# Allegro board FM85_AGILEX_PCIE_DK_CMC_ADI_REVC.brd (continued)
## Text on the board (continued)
User.18: C1448 | C1449 | C1439 | C1431 | C1177 | C1176 | R457 | C491 | C493 | C492 | R501 | R503 | R504 | R360 | R482 | R814 | R478 | R481 | R480 | R614 | C716 | R580 | R613 | R604 | R578 | R579 | R585 | R615 | R601 | R582 | R607 | R583 | R431 | C760 | R620 | R609 | R587 | R584 | R603 | R429 | R430 | R432 | R433 | R434 | R189 | R828 | R829 | R832 | R492 | R496 | R497 | C473 | R830 | C474 | R490 | R485 | R827 | C589 | C475 | C999 | C476 | R831 | R671 | R571 | R833 | C695 | R672 | R567 | C1000 | R568 | C692 | R834 | R970 | R668 | R572 | C1366 | R978 | R981 | R994 | C1345 | R995 | R980 | R801 | C1367 | C1346 | C1372 | R629 | R640 | R631 | FB27 | R688 | R683 | C850 | R692 | C849 | R538 | R537 | R532 | R534 | C772 | C610 | R625 | R639 | R536 | R531 | R529 | R630 | C774 | R632 | R684 | R903 | R694 | R686 | R65 | R901 | C196 | R73 | R74 | R52 | R905 | R899 | FB21 | FB20 | FB19 | FB18 | C146 | C158 | C155 | C145 | C153 | R475 | C156 | R474 | ST5 | C568 | C569 | ST4 | C100 | C109 | C395 | FB1 | C114 | C244 | R103 | R89 | C99 | C113 | C210 | R116 | R118 | R117 | R91 | C200 | C259 | C222 | C238 | C389 | C221 | C241 | C111 | C199 | C245 | C211 | C237 | C242 | C201 | C202 | C243 | C1138 | R92 | R105 | R93 | R106 | R220 | C1 | C10 | C352 | R221 | R973 | C351 | R952 | R975 | R951 | C1162 | R75 | C350 | C349 | C393 | C12 | R99 | R83 | C1224 | C1417 | C1054 | C203 | C239 | C209 | C235 | C348 | C347 | C1235 | C1416 | C207 | C233 | R37 | C2 | C11 | C1090 | C257 | C1426 | C1238 | C1234 | C205 | C1093 | R109 | R111 | R110 | C1236 | C1233 | C208 | C346 | C204 | C240 | C236 | C345 | R82 | R114 | C1232 | R113 | R115 | C258 | C225 | C206 | C234 | C9 | R120 | C1189 | C344 | C343 | C1285 | C1050 | C1407 | C1147 | C1148 | C47 | C61 | C342 | C1149 | R218 | C341 | R219 | R217 | C1043 | R146 | R215 | C1322 | C1099 | C1100 | R119 | C1280 | C339 | C1324 | C1272 | R214 | C338 | C1098 | C60 | R678 | R677 | R937 | R961 | R140 | C337 | R179 | C336 | R963 | C329 | C48 | C56 | R165 | R666 | R665 | C334 | C332 | C62 | C55 | C328 | C326 | R30 | R76 | C198 | R876 | C220 | C197 | C322 | R879 | C320 | R27 | R35 | R877 | C98 | R36 | C318 | C317 | R14 | R881 | R875 | R163 | C310 | C309 | C325 | C308 | R162 | R715 | C324 | R726 | R717 | C316 | C315 | R453 | C314 | C313 | C312 | C311 | C230 | C264 | C880 | C983 | R817 | C229 | C232 | R160 | R815 | R818 | R816 | R711 | R725 | C321 | C882 | R716 | R740 | C307 | R718 | C306 | R1000 | R1001 | C1389 | C1294 | C1293 | C290 | C275 | C282 | C267 | C1392 | R154 | C1342 | R173 | R153 | C435 | C271 | R149 | FB7 | C436 | C441 | C286 | C432 | C1343 | R445 | C462 | C444 | R447 | C560 | C459 | R446 | R451 | C456 | R239 | C280 | C265 | R444 | R436 | R390 | R399 | R437 | R403 | R438 | R439 | R393 | R389 | R441 | R388 | C557 | C555 | R442 | R837 | R836 | R212 | R464 | C524 | C391 | R469 | C567 | C539 | C514 | R468 | C553 | R466 | R211 | R424 | R463 | C482 | C481 | C518 | C517 | R425 | C549 | C521 | R467 | R323 | R324 | R421 | C548 | L14 | R462 | R322 | C515 | R325 | R420 | C546 | R423 | C495 | C526 | C528 | C738 | R418 | L12 | C532 | R130 | R135 | R417 | C301 | C488 | C487 | R134 | C302 | C512 | R595 | R341 | R346 | C730 | C304 | R345 | R340 | C303 | R344 | R339 | R125 | C735 | L13 | R332 | R596 | R860 | C295 | R864 | C490 | C489 | C739 | C296 | R349 | R353 | C503 | C509 | R348 | R352 | R354 | R355 | R347 | R351 | C506 | C507 | R350 | R773 | C505 | R781 | C499 | R381 | R342 | R382 | R343 | R317 | R318 | R319 | R320 | R412 | R338 | C496 | R375 | C1132 | R411 | C520 | C531 | R112 | R190 | R191 | R194 | R197 | R939 | R941 | C1128 | C1112 | C1130 | C1129 | C1279 | C1111 | C1122 | C1123 | C1121 | C1168 | C1175 | C1170 | C1421 | C1418 | C1419 | C1163 | C1097 | C1260 | C1244 | C1202 | C1094 | C1201 | C1095 | C1261 | C424 | C1096 | C1203 | C1425 | C1204 | C1029 | C1197 | C1198 | C1237 | C1192 | C1214 | C1042 | C1186 | C1210 | C1209 | C417 | C1159 | C1160 | C1255 | C1256 | C1283 | C1259 | C1258 | C1257 | C1262 | C1267 | C1058 | C1034 | C1041 | R866 | R856 | R867 | C1273 | R936 | R142 | R143 | R139 | R141 | R138 | C1263 | C1284 | C1307 | C1308 | C1320 | C1318 | C1126 | C1445 | C1319 | C1317 | C1125 | C1119 | C1124 | C1446 | C1154 | C1153 | R803 | R809 | R808 | C975 | R806 | R812 | R813 | R802 | R805 | R807 | R811 | C976 | R502 | R621 | R622 | C725 | R586 | C727 | R590 | TP10 | C356 | C357 | C360 | C361 | C364 | C365 | C368 | C369 | C379 | C380 | C383 | C384 | C387 | C388 | C375 | C376 | TP21 | C366 | C367 | C354 | C355 | C358 | C359 | C362 | C363 | R185 | R186 | ST27 | R669 | C373 | C374 | C381 | C382 | C385 | C386 | C377 | C378 | R670 | R676 | R679 | R972 | R967 | C1400 | C824 | R674 | R675 | R957 | R960 | TP20 | C986 | R792 | R852 | C1014 | C1015 | R846 | R826 | C998 | R794 | R798 | R790 | R796 | R795 | C966 | R793 | R799 | R800 | R789 | R825 | R850 | R849 | C1012 | C967 | TP22 | TP19 | TP11 | R551 | C599 | C600 | R559 | R506 | R513 | TP2 | R524 | R521 | R520 | R518 | R515 | R512 | R511 | R509 | TP4 | R527 | R526 | C607 | TP3 | TP16 | R533 | R550 | C633 | R553 | R554 | C713 | R573 | C701 | R576 | R577 | C690 | R563 | C675 | R565 | R566 | C668 | R558 | C656 | R560 | R561 | C700 | C674 | C655 | C632 | C699 | C673 | C654 | C631 | C697 | C671 | C652 | C629 | C664 | C665 | C645 | C644 | C682 | C684 | C709 | C708 | C711 | C688 | C666 | C647 | C1120 | C1265 | C1118 | C1117 | C1241 | C1045 | C1046 | C1242 | C1161 | C1180 | C1061 | C1183 | C1182 | C1104 | C1102 | C1103 | C1184 | C1181 | C1185 | C1325 | C1113 | C1101 | C1062 | C1239 | C1243 | C1047 | C1240 | C1152 | TP17 | C809 | C566 | C901 | R458 | R456 | R455 | R454 | R931 | R930 | C486 | R859 | R858 | R663 | C808 | R929 | R928 | R731 | R729 | R739 | R738 | R732 | C900 | R734 | R735 | R728 | R737 | R733 | R333 | R331 | R988 | R267 | R987 | R268 | R986 | C1332 | C446 | C445 | R234 | R233 | R230 | R229 | R223 | C448 | C447 | R985 | C1328 | R270 | R983 | R252 | R254 | R255 | R256 | R248 | R247 | R272 | R271 | R269 | R949 | C1331 | R170 | R172 | R263 | R264 | R237 | R238 | R235 | R236 | C453 | C454 | R784 | R783 | R788 | R786 | R426 | C952 | R785 | R787 | ST24 | R427 | C950 | R428 | R314 | R313 | C479 | R306 | R862 | R308 | C478 | ST29 | TP1 | R861 | C497 | C944 | R777 | ST23 | C498 | C948 | R776 | U35 | R363 | R361 | R359 | R356 | R364 | R362 | R358 | R357 | R982 | C561 | R365 | R368 | R366 | R370 | R369 | R367 | C572 | C573 | R477 | C1286 | R854 | R448 | R449 | R450 | C562 | R452 | R414 | R416 | R415 | R486 | R371 | ST26 | R484 | C579 | R479 | C715 | C751 | FB24 | R617 | R612 | ST3 | R588 | C750 | R616 | R618 | R619 | R589 | R608 | R611 | R581 | C720 | C726 | R602 | R606 | R187 | R293 | R487 | R488 | C587 | R489 | C1399 | R188 | R292 | R291 | R303 | R304 | R294 | R993 | C1397 | R996 | FB13 | R493 | R491 | R495 | R997 | R546 | R547 | C1398 | C472 | R998 | C471 | ST10 | R569 | R570 | C694 | C370 | C371 | C1368 | R969 | R933 | R932 | C1395 | R935 | R934 | C1396 | R971 | C1388 | C1347 | R958 | R976 | R965 | R966 | R977 | C685 | ST32 | C1369 | R959 | C1356 | R964 | R955 | ST28 | ST25 | R979 | C1348 | C687 | ST31 | R624 | R627 | R633 | C372 | ST13 | R690 | C848 | R626 | R628 | C782 | R641 | R634 | FB17 | R687 | C214 | C248 | C602 | C223 | C250 | C613 | R564 | R507 | R508 | R516 | R517 | R575 | C609 | R530 | R535 | R70 | R72 | R906 | R909 | C191 | R911 | R898 | R68 | R67 | R900 | R55 | R689 | R685 | R695 | C858 | R682 | C773 | R635 | ST6 | C611 | C617 | C612 | C616 | R926 | C194 | R51 | R57 | R59 | R914 | R915 | R902 | R896 | R892 | R894 | R691 | R680 | R693 | R681 | R53 | R61 | R60 | R54 | R58 | R913 | R904 | R895 | R893 | R63 | R56 | C192 | R62 | R908 | R907 | R910 | R912 | C653 | C698 | C630 | C672 | R66 | R897 | R71 | R69 | C178 | C169 | C186 | C165 | C177 | C151 | C160 | C163 | C710 | C683 | C663 | C646 | C189 | C185 | C175 | C187 | R48 | C190 | C176 | C150 | C188 | C161 | R46 | C172 | C180 | C182 | C181 | C166 | C179 | C148 | C154 | C162 | R555 | R522 | R476 | R465 | C168 | R556 | R528 | C167 | C571 | C157 | C164 | R47 | C159 | C183 | C174 | C147 | C184 | R45 | C173 | C570 | C1167 | R470 | R471 | R472 | R473 | C131 | C137 | C136 | C118 | C134 | C102 | C107 | C117 | C143 | C144 | C128 | C123 | R42 | C1116 | C1127 | C122 | C129 | C108 | C101 | C142 | R40 | C126 | R88 | R87 | R90 | R104 | C132 | C135 | C141 | C120 | C133 | C104 | C112 | C116 | R927 | C140 | C121 | R196 | R108 | R195 | C110 | C119 | R41 | C139 | C130 | C115 | C105 | C138 | R39 | C127 | ST12 | ST11 | C1247 | C33 | C41 | C42 | C21 | C36 | C4 | C13 | C18 | C213 | C226 | C251 | C249 | C215 | C224 | C247 | C260 | C23 | C24 | C16 | C22 | R3 | C25 | C30 | C14 | C3 | C46 | R1 | C28 | C1092 | R38 | C35 | C37 | C40 | C20 | C34 | C7 | C15 | C19 | C43 | R98 | C38 | C1091 | C31 | C39 | R4 | R97 | C44 | C32 | C17 | C6 | C45 | R2 | C29 | R79 | C1178 | C81 | C83 | C89 | C68 | R102 | R86 | C80 | C50 | C63 | C64 | C1179 | C69 | C88 | R145 | C263 | C58 | C67 | R9 | R216 | R209 | C256 | C92 | C78 | C59 | C49 | C87 | R7 | C74 | C231 | R213 | C392 | C1326 | R178 | C79 | C86 | C91 | C66 | R210 | C82 | C52 | C57 | C65 | C90 | C85 | R81 | C76 | C84 | R10 | C70 | C77 | C53 | C71 | R8 | C75 | R80 | R34 | R882 | R885 | R887 | R874 | R17 | C93 | R32 | R29 | C892 | C94 | R865 | R13 | R19 | R21 | R890 | R891 | R878 | R872 | R868 | R870 | R15 | ST16 | ST15 | R23 | R22 | R16 | R20 | R157 | R889 | R880 | R871 | R869 | R156 | R999 | R25 | R18 | C95 | R24 | R710 | R713 | R719 | R884 | R883 | R886 | R888 | R28 | R873 | R31 | R33 | R714 | C890 | R727 | R712 | R720 | R460 | R921 | C1313 | R925 | R923 | R819 | R656 | ST20 | C1312 | R820 | C985 | C565 | ST9 | R85 | R101 | R84 | R100 | C1310 | C977 | R662 | R660 | R917 | R329 | R330 | C483 | ST18 | R916 | R918 | R920 | FB40 | C881 | R721 | R605 | R610 | ST17 | C1391 | C1390 | R183 | R184 | C353 | FB10 | R942 | R327 | R328 | C484 | C438 | FB8 | FB6 | R151 | R155 | R435 | ST30 | C558 | C434 | C433 | C430 | C442 | C443 | C428 | C431 | C340 | R174 | R440 | R443 | R224 | R948 | R946 | C461 | C458 | R228 | C427 | FB5 | C440 | C425 | C426 | C437 | C439 | C429 | R129 | R128 | R124 | R133 | C460 | C457 | C463 | R126 | R127 | R123 | R132 | R122 | R121 | FB9 | R387 | R386 | R392 | R394 | R395 | R400 | R379 | R158 | R422 | R419 | R175 | R171 | R380 | R401 | R397 | R398 | R396 | R402 | C559 | C542 | C536 | C552 | C556 | C390 | C534 | C535 | C1006 | C551 | C533 | R840 | R839 | R838 | C511 | C554 | C519 | C300 | C299 | C540 | C522 | R598 | R591 | R593 | C529 | C530 | C545 | C538 | C537 | R597 | ST2 | C729 | L11 | C733 | ST1 | R599 | R385 | C305 | C508 | C510 | R594 | R592 | R600 | R384 | C501 | R137 | R131 | C298 | C297 | R136 | R204 | R206 | R207 | R208 | R316 | R315 | R857 | R337 | R321 | R326 | R413 | R409 | R408 | R287 | R286 | R285 | R284 | R383 | R374 | C504 | R373 | R288 | R281 | R282 | R283 | R203 | R199 | R205 | R200 | R202 | R201 | R198 | C1447 | C1248 | C1131 | C1114 | C396 | C1173 | C1315 | C1169 | C1144 | C1146 | C1145 | C1408 | C1040 | C1048 | C1420 | C1038 | C1039 | C1057 | C1423 | C1053 | C1422 | C1409 | C1403 | C1410 | C1245 | C1424 | C420 | C1030 | C1223 | C1056 | C419 | C1225 | C423 | C1226 | C1139 | C1020 | C1135 | C1411 | C1196 | C1055 | C1220 | C1219 | C1199 | C1140 | C1031 | C1136 | C1412 | C1218 | C1221 | C1193 | C1037 | C1049 | C1428 | C1141 | C1137 | C1028 | C1022 | C1213 | C1194 | C1191 | C1021 | C1044 | C1142 | C1143 | C1415 | C1427 | C1215 | C1166 | C1216 | C418 | C1429 | C1187 | C1188 | C1052 | C422 | C1023 | C1051 | C1165 | C1430 | C421 | C1413 | C1211 | C1027 | C1024 | C1208 | C1404 | C1406 | C1401 | C1025 | C416 | C1033 | C1032 | C1402 | C1414 | C1270 | C1269 | C1172 | C1171 | C1019 | C1026 | C1405 | C1150 | C1151 | C1174 | C1036 | C1059 | C1035 | C1316 | C1060 | C1271 | C397 | C1115 | C1314 | C1268 | C1323 | C1246 | C1321 | C1251 | C1250 | C1249 | R182 | R144 | C544 | C527 | R406 | C516 | R404 | C525 | C543 | R391 | C1304 | R804 | C972 | R810 | R498 | R500 | R505 | R499 | C597 | R483 | C581 | R494 | R822 | R821 | R824 | C821 | R823 | C1385 | C997 | C825 | C1364 | C826 | R673 | C962 | C1287 | C1288 | R791 | R851 | R847 | C1013 | R797 | R841 | R848 | R845 | C1018 | R844 | R843 | R842 | C1371 | C1350 | C781 | C857 | C606 | R523 | C604 | C603 | C605 | R519 | R574 | C601 | R562 | R514 | R557 | C598 | R549 | R510 | C608 | C780 | R525 | C856 | C615 | C614 | C649 | C327 | R164 | C335 | R169 | C1200 | C1222 | C1227 | C1195 | C1190 | C1212 | C1217 | C1164 | C1205 | R168 | C333 | C1155 | R167 | C331 | C888 | C485 | R336 | R335 | R760 | C323 | R161 | C807 | C920 | R759 | R659 | R657 | R757 | R661 | R461 | C919 | R459 | R753 | R756 | C804 | R754 | C564 | C563 | R658 | R755 | R664 | R758 | R667 | R736 | C896 | R730 | C889 | C1394 | C330 | C468 | R166 | C467 | C319 | C1330 | C1329 | R159 | C1393 | R945 | R943 | C466 | C1336 | R947 | C465 | R152 | R225 | C450 | R150 | R984 | C1327 | C449 | R245 | R944 | R232 | R246 | R148 | R950 | R231 | R241 | R147 | R259 | R953 | C452 | R242 | R262 | C451 | C1334 | R250 | R244 | R249 | R240 | R243 | R260 | R226 | R251 | R227 | R257 | R253 | R258 | R177 | C464 | C455 | R261 | R176 | C958 | R311 | R310 | R312 | R309 | C480 | R305 | R307 | C477 | R863 | R372 | R377 | R376 | R378 | R780 | FB16 | C938 | 1 | 2 | 3 | 4 | 5 | 6 | 38 | 7 | 37 | 8 | 36 | 9 | 35 | 10 | 34 | 11 | 33 | 12 | 32 | 13 | 31 | 14 | 30 | 15 | 39 | 29 | 16 | 28 | 17 | 27 | 18 | 26 | 19 | 25 | 24 | 23 | 22 | 21 | 20 | C415 | FB31 | 57 | 58 | 59 | 60 | 61 | 62 | 63 | 64 | 65 | 66 | 67 | 68 | 69 | 70 | 71 | 72 | 73 | 74 | 75 | 76 | 56 | 55 | 54 | 53 | 52 | 51 | 50 | 49 | 48 | 47 | 46 | 45 | 44 | 43 | 42 | 41 | 40 | C827 | R956 | C988 | C990 | C193 | C992 | C991 | C152 | C171 | C170 | C149 | C125 | C103 | C124 | C106 | C27 | C26 | C72 | C51 | C73 | C54 | FB29 | C96 | C984 | C815 | C980 | C819 | C817 | R94 | R107 | C816 | C749 | C1340 | C291 | C276 | C283 | C268 | C284 | C270 | C285 | C292 | C269 | C272 | C278 | C287 | C1341 | C281 | C266 | C547 | C736 | C737 | C541 | C550 | C734 | C731 | C1303 | C941 | 77 | TP14 | U41 | TP18 | C949 | C394 | C410 | C412 | C411 | C409 | C408 | C414 | C413 | C891 | C405 | C404 | C406 | FB30 | FB33 | FB28 | C1001 | TP15 | C989 | C987 | C829 | C828 | C830 | C996 | C995 | C993 | C1010 | C691 | C669 | C1107 | C1109 | C1110 | C1108 | C1105 | C1106 | C805 | C957 | C951 | C1305 | C946 | C686 | C833 | C837 | C838 | C835 | R540 | R539 | FB25 | C696 | C670 | C651 | C628 | C712 | C689 | C667 | C648 | C703 | C702 | C677 | C676 | C658 | C657 | C638 | C639 | R552 | C1266 | C1134 | C1133 | C1277 | C1450 | C1064 | C1069 | C1065 | C1066 | C1444 | C1070 | C1068 | C1067 | C1063 | C1443 | C407 | FB32 | FB41 | C978 | C981 | C982 | C1311 | C979 | C1309 | C277 | C293 | C289 | C288 | C274 | C273 | U27 | C728 | U26 | C523 | C513 | C732 | C1306 | C500 | C945 | U17 | U39 | D4 | D3 | D2 | D1 | C823 | C1382 | C822 | C1360 | C1016 | C1017 | C994 | C1387 | C1386 | C1008 | C1351 | C1264 | C650 | C714 | C806 | C812 | C813 | C811 | C810 | C1333 | C1335 | C502 | C1438 | C723 | C721 | C718 | C973 | C968 | C582 | C767 | C779 | C841 | C855 | C777 | C965 | C768 | C964 | C769 | C854 | C840 | C778 | C852 | C775 | C766 | C853 | C842 | C627 | C619 | C620 | C626 | C784 | C785 | C783 | C874 | C893 | C895 | C883 | C885 | C884 | C876 | C886 | C877 | C875 | C887 | R835 | C294 | C279 | S5 | S4 | S3 | S2 | S1 | C759 | C756 | C758 | U44 | U45 | C745 | C748 | C744 | C743 | TP8 | TP9 | U46 | U48 | U85 | C834 | FB26 | C921 | EU1 | C922 | Y2 | U80 | U77 | Y3 | U79 | HW1 | C494 | C757 | C752 | C753 | C755 | C754 | C577 | C575 | C578 | C576 | C740 | C747 | C746 | C707 | C705 | C681 | C680 | C662 | C661 | C643 | C642 | C706 | C679 | C660 | C641 | C195 | C1432 | C1437 | C1435 | C1436 | C1433 | C219 | C255 | C217 | C252 | C212 | C246 | C1441 | C216 | C218 | C254 | C253 | C1440 | C1442 | C228 | C262 | C923 | C227 | C261 | Q11 | Q9 | Q12 | C724 | C717 | U53 | C722 | C719 | C974 | C969 | C971 | C970 | C762 | C776 | C832 | C845 | C960 | C959 | C847 | C961 | C963 | C846 | C763 | C851 | C839 | C897 | C898 | C871 | C894 | C899 | C820 | C818 | C870 | C1338 | C1339 | C5 | C8 | C1004 | MH1 | MH3 | SMT040X040 | QSFPDD0 | G | Y | QSFPDD1 | D | C | TM | PAD-SMT052X063 | B | A | TCK | EXTERNAL JTAG | TDO | CLK_OUT | CLK_IN | TMS | ENPIRION DONGLE | D11:FPGA_CONF_DONE | D9:OVERTEMPn | TDI | FPGA_3V3 | 0 | POWER | PAD-SMT080X090 | A1 | A2 | A3 | A4 | A5 | A6 | A7 | A8 | A9 | A10 | A11 | A12 | A13 | A14 | A15 | A16 | A17 | A18 | A19 | A20 | A21 | A22 | A23 | A24 | A25 | A26 | A27 | A28 | A29 | A30 | A31 | A32 | A33 | A34 | A35 | A36 | A37 | B1 | B2 | B3 | B4 | B5 | B6 | B7 | B8 | B9 | B10 | B11 | B12 | B13 | B14 | B15 | B16 | B17 | B18 | B19 | B20 | B21 | B22 | B23 | B24 | B25 | B26 | B27 | B28 | B29 | B30 | B31 | B32 | B33 | B34 | B35 | B36 | B37 | MH2 | MH4 | 100 | 99 | 98 | 97 | 96 | 145 | 95 | 146 | 94 | 102 | 93 | 147 | 92 | 91 | 101 | 103 | 104 | 148 | 90 | 149 | 89 | 88 | 150 | 87 | 86 | 151 | 85 | 84 | 152 | 83 | 153 | 82 | 154 | 81 | 80 | 79 | 78 | 155 | 156 | E1 | F1 | G1 | H1 | J1 | K1 | L1 | M1 | N1 | P1 | T1 | 157 | E2 | F2 | G2 | H2 | J2 | K2 | L2 | M2 | N2 | P2 | T2 | 158 | E3 | F3 | G3 | H3 | J3 | K3 | L3 | M3 | N3 | P3 | T3 | 159 | 160 | 161 | 162 | D7 | E7 | F7 | G7 | H7 | J7 | K7 | L7 | M7 | N7 | P7 | T7 | 163 | D8 | E8 | F8 | G8 | H8 | J8 | K8 | L8 | M8 | N8 | P8 | T8 | 164 | D9 | E9 | F9 | G9 | H9 | J9 | K9 | L9 | M9 | N9 | P9 | T9 | 165 | 166 | 167 | 168 | 169 | 170 | 171 | 172 | 173 | 174 | 175 | 176 | 177 | 178 | 179 | 180 | 181 | 182 | 183 | 184 | 185 | 186 | 187 | 188 | 189 | 190 | 191 | 192 | 193 | 194 | 195 | 196 | 197 | 198 | 199 | 200 | 201 | AB1 | AH1 | AP1 | BA1 | BG1 | BN1 | BW1 | CE1 | CL1 | CV1 | DD1 | DK1 | DT1 | EB1 | EH1 | ER1 | FA1 | FG1 | FN1 | FW1 | GE1 | GM1 | GV1 | HD1 | HK1 | HT1 | JC1 | JJ1 | JR1 | KA1 | KG1 | KN1 | KY1 | LF1 | 202 | U2 | LR2 | LW2 | MC2 | MF2 | AE3 | AL3 | AU3 | BD3 | BK3 | BT3 | CB3 | CH3 | CP3 | DA3 | DG3 | DN3 | DW3 | EE3 | EM3 | EV3 | FD3 | FK3 | FT3 | GB3 | GJ3 | GR3 | HA3 | HG3 | HN3 | HW3 | JF3 | JM3 | JV3 | KD3 | KK3 | KT3 | LC3 | LJ3 | H4 | L4 | W4 | LU4 | MA4 | MD4 | 203 | LR5 | LW5 | MC5 | MF5 | MK5 | F5 | J5 | N5 | U5 | AB6 | AH6 | AP6 | BA6 | BG6 | BN6 | BW6 | CE6 | CL6 | CV6 | DD6 | DK6 | DT6 | EB6 | EH6 | ER6 | FA6 | FG6 | FN6 | FW6 | GE6 | GM6 | GV6 | HD6 | HK6 | HT6 | JC6 | JJ6 | JR6 | KA6 | KG6 | KN6 | KY6 | LF6 | 204 | LN7 | LU7 | MA7 | MD7 | MH7 | W7 | AE8 | AL8 | AU8 | BD8 | BK8 | BT8 | CB8 | CH8 | CP8 | DA8 | DG8 | DN8 | DW8 | EE8 | EM8 | EV8 | FD8 | FK8 | FT8 | GB8 | GJ8 | GR8 | HA8 | HG8 | HN8 | HW8 | JF8 | JM8 | JV8 | KD8 | KK8 | KT8 | LC8 | 205 | LR9 | LW9 | MC9 | MF9 | MK9 | U9 | AB10 | AH10 | AP10 | BA10 | BG10 | BN10 | BW10 | CE10 | CL10 | CV10 | DD10 | DK10 | DT10 | EB10 | EH10 | ER10 | FA10 | FG10 | FN10 | FW10 | GE10 | GM10 | GV10 | HD10 | HK10 | HT10 | JC10 | JJ10 | JR10 | KA10 | KG10 | KN10 | KY10 | LF10 | 206 | LN11 | LU11 | MA11 | MD11 | MH11 | D11 | H11 | R11 | W11 | AE12 | AL12 | AU12 | BD12 | BK12 | BT12 | CB12 | CH12 | CP12 | DA12 | DG12 | DN12 | DW12 | EE12 | EM12 | EV12 | FD12 | FK12 | FT12 | GB12 | GJ12 | GR12 | HA12 | HG12 | HN12 | HW12 | JF12 | JM12 | JV12 | KD12 | KK12 | KT12 | LC12 | 207 | LR13 | LW13 | MC13 | MF13 | MK13 | F13 | J13 | N13 | U13 | 208 | AB14 | AH14 | AP14 | BA14 | BG14 | BN14 | BW14 | CE14 | CL14 | CV14 | DD14 | DK14 | DT14 | EB14 | EH14 | ER14 | FA14 | FG14 | FN14 | FW14 | GE14 | GM14 | GV14 | HD14 | HK14 | HT14 | JC14 | JJ14 | JR14 | KA14 | KG14 | KN14 | KY14 | LF14 | LN15 | LU15 | MA15 | MD15 | MH15 | D15 | H15 | L15 | 209 | AE16 | AL16 | LJ16 | AU16 | BD16 | BK16 | BT16 | CB16 | CH16 | CP16 | DA16 | DG16 | DN16 | DW16 | EE16 | EM16 | EV16 | FD16 | FK16 | FT16 | GB16 | GJ16 | GR16 | HA16 | HG16 | HN16 | HW16 | JF16 | JM16 | JV16 | KD16 | KK16 | KT16 | LC16 | LR17 | LW17 | MC17 | MF17 | MK17 | F17 | J17 | N17 | 210 | AB18 | AH18 | AP18 | BA18 | BG18 | BN18 | BW18 | CE18 | CL18 | CV18 | DD18 | DK18 | DT18 | EB18 | EH18 | ER18 | FA18 | FG18 | FN18 | FW18 | GE18 | GM18 | GV18 | HD18 | HK18 | HT18 | JC18 | JJ18 | JR18 | KA18 | KG18 | KN18 | KY18 | LF18 | LN19 | LU19 | MA19 | MD19 | MH19 | D19 | H19 | L19 | 211 | AE20 | AL20 | LJ20 | AU20 | BD20 | BK20 | BT20 | CB20 | CH20 | CP20 | DA20 | DG20 | DN20 | DW20 | EE20 | EM20 | EV20 | FD20 | FK20 | FT20 | GB20 | GJ20 | GR20 | HA20 | HG20 | HN20 | HW20 | JF20 | JM20 | JV20 | KD20 | KK20 | KT20 | LC20 | LR21 | LW21 | MC21 | MF21 | MK21 | F21 | J21 | N21 | U21 | 212 | AB22 | AH22 | AP22 | BA22 | BG22 | BN22 | BW22 | CE22 | CL22 | CV22 | DD22 | DK22 | DT22 | EB22 | EH22 | ER22 | FA22 | FG22 | FN22 | FW22 | GE22 | GM22 | GV22 | HD22 | HK22 | HT22 | JC22 | JJ22 | JR22 | KA22 | KG22 | KN22 | KY22 | LF22 | LN23 | LU23 | MA23 | MD23 | MH23 | D23 | H23 | L23 | 213 | AE24 | AL24 | LJ24 | AU24 | BD24 | BK24 | BT24 | CB24 | CH24 | CP24 | DA24 | DG24 | DN24 | DW24 | EE24 | EM24 | EV24 | FD24 | FK24 | FT24 | GB24 | GJ24 | GR24 | HA24 | HG24 | HN24 | HW24 | JF24 | JM24 | JV24 | KD24 | KK24 | KT24 | LC24 | LR25 | LW25 | MC25 | MF25 | MK25 | F25 | J25 | N25 | U25 | 214 | AD26 | AK26 | AT26 | AY26 | BF26 | BM26 | BV26 | CD26 | CK26 | CR26 | CY26 | DF26 | DM26 | DV26 | ED26 | EJ26 | EP26 | EY26 | FF26 | FM26 | FV26 | GD26 | GH26 | GP26 | GY26 | HF26 | HM26 | HV26 | JB26 | JH26 | JP26 | JY26 | KF26 | KM26 | KU26 | LB26 | LH26 | LN26 | LU26 | MA26 | MD26 | MH26 | D26 | H26 | L26 | R26 | W26 | 215 | LR27 | LW27 | MC27 | MF27 | AA27 | AG27 | AN27 | AV27 | BC27 | BJ27 | BR27 | CA27 | CG27 | CN27 | CU27 | DC27 | DJ27 | DR27 | EA27 | EG27 | EL27 | EU27 | FC27 | FJ27 | FR27 | GA27 | GF27 | GL27 | GU27 | HC27 | HJ27 | HR27 | HY27 | JE27 | JL27 | JU27 | KC27 | KJ27 | KR27 | KW27 | LE27 | LL27 | MK27 | F27 | J27 | N27 | 216 | LB28 | LN28 | LU28 | MA28 | MD28 | MH28 | AD28 | AK28 | AT28 | AY28 | BF28 | BM28 | BV28 | CD28 | CK28 | CR28 | CY28 | DF28 | DM28 | DV28 | ED28 | EJ28 | EP28 | EY28 | FF28 | FM28 | FV28 | GD28 | GH28 | GP28 | GY28 | HF28 | HM28 | HV28 | JB28 | JH28 | JP28 | JY28 | KF28 | KM28 | KU28 | LH28 | D28 | H28 | L28 | W28 | 217 | LR29 | LW29 | MC29 | MF29 | DJ29 | DR29 | EA29 | EG29 | EL29 | EU29 | FC29 | FJ29 | FR29 | GA29 | GF29 | GL29 | GU29 | HC29 | HJ29 | HR29 | HY29 | JE29 | JL29 | JU29 | KC29 | KJ29 | KR29 | KW29 | LE29 | LL29 | AA29 | AG29 | AN29 | AV29 | BC29 | BJ29 | BR29 | CA29 | CG29 | CN29 | CU29 | DC29 | MK29 | F29 | J29 | N29 | U29 | LB30 | LN30 | LU30 | MA30 | MD30 | MH30 | AD30 | AK30 | AT30 | AY30 | BF30 | BM30 | BV30 | CD30 | CK30 | CR30 | CY30 | DF30 | DM30 | DV30 | ED30 | EJ30 | EP30 | EY30 | FF30 | FM30 | FV30 | GD30 | GH30 | GP30 | GY30 | HF30 | HM30 | HV30 | JB30 | JH30 | JP30 | JY30 | KF30 | KM30 | KU30 | LH30 | D30 | H30 | L30 | W30 | 218 | LR31 | LW31 | MC31 | MF31 | DJ31 | DR31 | EA31 | EG31 | EL31 | EU31 | FC31 | FJ31 | FR31 | GA31 | GF31 | GL31 | GU31 | HC31 | HJ31 | HR31 | HY31 | JE31 | JL31 | JU31 | KC31 | KJ31 | KW31 | LE31 | LL31 | KR31 | AA31 | AG31 | AN31 | AV31 | BC31 | BJ31 | BR31 | CA31 | CG31 | CN31 | CU31 | DC31 | MK31 | F31 | J31 | N31 | U31 | 219 | LB32 | LN32 | LU32 | MA32 | MD32 | MH32 | AD32 | AK32 | AT32 | AY32 | BF32 | BM32 | BV32 | CD32 | CK32 | CR32 | CY32 | DF32 | DM32 | DV32 | ED32 | EJ32 | EP32 | EY32 | FF32 | FM32 | FV32 | GD32 | GH32 | GP32 | GY32 | HF32 | HM32 | HV32 | JB32 | JH32 | JP32 | JY32 | KF32 | KM32 | KU32 | LH32 | D32 | H32 | L32 | W32 | 220 | LR33 | LW33 | MC33 | MF33 | DJ33 | DR33 | EA33 | EG33 | EL33 | EU33 | FC33 | FJ33 | FR33 | GA33 | GF33 | GL33 | GU33 | HC33 | HJ33 | HR33 | HY33 | JE33 | JL33 | JU33 | KC33 | KJ33 | KW33 | LE33 | LL33 | KR33 | AA33 | AG33 | AN33 | AV33 | BC33 | BJ33 | BR33 | CA33 | CG33 | CN33 | CU33 | DC33 | MK33 | F33 | J33 | N33 | U33 | 221 | LB34 | LN34 | LU34 | MA34 | MD34 | MH34 | AD34 | AK34 | AT34 | AY34 | BF34 | BM34 | BV34 | CD34 | CK34 | CR34 | CY34 | DF34 | DM34 | DV34 | ED34 | EJ34 | EP34 | EY34 | FF34 | FM34 | FV34 | GD34 | GH34 | GP34 | GY34 | HF34 | HM34 | HV34 | JB34 | JH34 | JP34 | JY34 | KF34 | KM34 | KU34 | LH34 | D34 | H34 | L34 | W34 | LR35 | LW35 | MC35 | MF35 | DJ35 | DR35 | EA35 | EG35 | EL35 | EU35 | FC35 | FJ35 | FR35 | GA35 | GF35 | GL35 | GU35 | HC35 | HJ35 | HR35 | HY35 | JE35 | JL35 | JU35 | KC35 | KJ35 | KW35 | LE35 | LL35 | KR35 | AA35 | AG35 | AN35 | AV35 | BC35 | BJ35 | BR35 | CA35 | CG35 | CN35 | CU35 | DC35 | MK35 | F35 | J35 | N35 | LB36 | LN36 | LU36 | MA36 | MD36 | MH36 | AD36 | AK36 | AT36 | AY36 | BF36 | BM36 | BV36 | CD36 | CK36 | CR36 | CY36 | DF36 | DM36 | DV36 | ED36 | EJ36 | EP36 | EY36 | FF36 | FM36 | FV36 | GD36 | GH36 | GP36 | GY36 | HF36 | HM36 | HV36 | JB36 | JH36 | JP36 | JY36 | KF36 | KM36 | KU36 | LH36 | D36 | H36 | L36 | W36 | LR37 | LW37 | MC37 | MF37 | DJ37 | DR37 | EA37 | EG37 | EL37 | EU37 | FC37 | FJ37 | FR37 | GA37 | GF37 | GL37 | GU37 | HC37 | HJ37 | HR37 | HY37 | JE37 | JL37 | JU37 | KC37 | KJ37 | KW37 | LE37 | LL37 | KR37 | AA37 | AG37 | AN37 | AV37 | BC37 | BJ37 | BR37 | CA37 | CG37 | CN37 | CU37 | DC37 | MK37 | F37 | J37 | N37 | U37 | LB38 | LN38 | LU38 | MA38 | MD38 | MH38 | AD38 | AK38 | AT38 | AY38 | BF38 | BM38 | BV38 | CD38 | CK38 | CR38 | CY38 | DF38 | DM38 | DV38 | ED38 | EJ38 | EP38 | EY38 | FF38 | FM38 | FV38 | GD38 | GH38 | GP38 | GY38 | HF38 | HM38 | HV38 | JB38 | JH38 | JP38 | JY38 | KF38 | KM38 | KU38 | LH38 | D38 | H38 | L38 | W38 | LR39 | LW39 | MC39 | MF39 | DJ39 | DR39 | EA39 | EG39 | EL39 | EU39 | FC39 | FJ39 | FR39 | GA39 | GF39 | GL39 | GU39 | HC39 | HJ39 | HR39 | HY39 | JE39 | JL39 | JU39 | KC39 | KJ39 | KW39 | LE39 | LL39 | KR39 | AA39 | AG39 | AN39 | AV39 | BC39 | BJ39 | BR39 | CA39 | CG39 | CN39 | CU39 | DC39 | B39 | MK39 | F39 | J39 | N39 | LB40 | LN40 | LU40 | MA40 | MD40 | MH40 | AD40 | AK40 | AT40 | AY40 | BF40 | BM40 | BV40 | CD40 | CK40 | CR40 | CY40 | DF40 | DM40 | DV40 | ED40 | EJ40 | EP40 | EY40 | FF40 | FM40 | FV40 | GD40 | GH40 | GP40 | GY40 | HF40 | HM40 | HV40 | JB40 | JH40 | JP40 | JY40 | KF40 | KM40 | KU40 | LH40 | D40 | H40 | L40 | W40 | 222 | LR41 | LW41 | MC41 | MF41 | DJ41 | HJ41 | HR41 | HY41 | JE41 | JL41 | JU41 | KC41 | KJ41 | KW41 | LE41 | LL41 | HC41 | KR41 | AA41 | AG41 | AN41 | AV41 | BC41 | BJ41 | BR41 | CA41 | CG41 | CN41 | CU41 | DC41 | B41 | MK41 | F41 | J41 | N41 | 223 | LB42 | LN42 | LU42 | MA42 | MD42 | MH42 | GY42 | HF42 | AD42 | AK42 | AT42 | AY42 | BF42 | BM42 | BV42 | CD42 | CK42 | CR42 | CY42 | DF42 | DM42 | HM42 | HV42 | JB42 | JH42 | JP42 | JY42 | KF42 | KM42 | KU42 | LH42 | D42 | H42 | L42 | W42 | 224 | LR43 | LW43 | MC43 | MF43 | DJ43 | HJ43 | HR43 | HY43 | JE43 | JL43 | JU43 | KC43 | KJ43 | KW43 | LE43 | LL43 | HC43 | KR43 | AA43 | AG43 | AN43 | AV43 | BC43 | BJ43 | BR43 | CA43 | CG43 | CN43 | CU43 | DC43 | B43 | MK43 | F43 | J43 | N43 | U43 | 225 | LB44 | LN44 | LU44 | MA44 | MD44 | MH44 | GY44 | HF44 | AD44 | AK44 | AT44 | AY44 | BF44 | BM44 | BV44 | CD44 | CK44 | CR44 | CY44 | DF44 | DM44 | HM44 | HV44 | JB44 | JH44 | JP44 | JY44 | KF44 | KM44 | KU44 | LH44 | D44 | H44 | L44 | R44 | W44 | 226 | LR45 | LW45 | MC45 | MF45 | DJ45 | HJ45 | HR45 | HY45 | JE45 | JL45 | JU45 | KC45 | KJ45 | KW45 | LE45 | LL45 | HC45 | KR45 | AA45 | AG45 | AN45 | AV45 | BC45 | BJ45 | BR45 | CA45 | CG45 | CN45 | CU45 | DC45 | B45 | MK45 | F45 | J45 | N45 | LB46 | LN46 | LU46 | MA46 | MD46 | MH46 | GY46 | HF46 | AD46 | AK46 | AT46 | AY46 | BF46 | BM46 | BV46 | CD46 | CK46 | CR46 | CY46 | DF46 | DM46 | HM46 | HV46 | JB46 | JH46 | JP46 | JY46 | KF46 | KM46 | KU46 | LH46 | D46 | H46 | L46 | W46 | 227 | LR47 | LW47 | MC47 | MF47 | DJ47 | HJ47 | HR47 | HY47 | JE47 | JL47 | JU47 | KC47 | KJ47 | KW47 | LE47 | LL47 | HC47 | KR47 | AA47 | AG47 | AN47 | AV47 | BC47 | BJ47 | BR47 | CA47 | CG47 | CN47 | CU47 | DC47 | B47 | MK47 | F47 | J47 | N47 | U47 | 228 | LB48 | LN48 | LU48 | MA48 | MD48 | MH48 | GY48 | HF48 | AD48 | AK48 | AT48 | AY48 | BF48 | BM48 | BV48 | CD48 | CK48 | CR48 | CY48 | DF48 | DM48 | HM48 | HV48 | JB48 | JH48 | JP48 | JY48 | KF48 | KM48 | KU48 | LH48 | D48 | H48 | L48 | W48 | 229 | LR49 | LW49 | MC49 | MF49 | DJ49 | HJ49 | HR49 | HY49 | JE49 | JL49 | JU49 | KC49 | KJ49 | KW49 | LE49 | LL49 | HC49 | KR49 | AA49 | AG49 | AN49 | AV49 | BC49 | BJ49 | BR49 | CA49 | CG49 | CN49 | CU49 | DC49 | B49 | MK49 | F49 | J49 | N49 | U49 | 230 | LB50 | LN50 | LU50 | MA50 | MD50 | MH50 | GY50 | HF50 | AD50 | AK50 | AT50 | AY50 | BF50 | BM50 | BV50 | CD50 | CK50 | CR50 | CY50 | DF50 | DM50 | HM50 | HV50 | JB50 | JH50 | JP50 | JY50 | KF50 | KM50 | KU50 | LH50 | D50 | H50 | L50 | R50 | W50 | 231 | LR51 | LW51 | MC51 | MF51 | DJ51 | HJ51 | HR51 | HY51 | JE51 | JL51 | JU51 | KC51 | KJ51 | KW51 | LE51 | LL51 | HC51 | KR51 | AA51 | AG51 | AN51 | AV51 | BC51 | BJ51 | BR51 | CA51 | CG51 | CN51 | CU51 | DC51 | B51 | MK51 | F51 | J51 | N51 | U51 | 232 | LB52 | LN52 | LU52 | MA52 | MD52 | MH52 | GY52 | HF52 | AD52 | AK52 | AT52 | AY52 | BF52 | BM52 | BV52 | CD52 | CK52 | CR52 | CY52 | DF52 | DM52 | HM52 | HV52 | JB52 | JH52 | JP52 | JY52 | KF52 | KM52 | KU52 | LH52 | D52 | H52 | L52 | W52 | 233 | LR53 | LW53 | MC53 | MF53 | DJ53 | HJ53 | HR53 | HY53 | JE53 | JL53 | JU53 | KC53 | KJ53 | KW53 | LE53 | LL53 | DR53 | EA53 | EG53 | EL53 | EU53 | FC53 | FJ53 | FR53 | GA53 | GF53 | GL53 | GU53 | HC53 | KR53 | AA53 | AG53 | AN53 | AV53 | BC53 | BJ53 | BR53 | CA53 | CG53 | CN53 | CU53 | DC53 | B53 | MK53 | F53 | J53 | N53 | 234 | LB54 | LN54 | LU54 | MA54 | MD54 | MH54 | DV54 | ED54 | EJ54 | EP54 | EY54 | FF54 | FM54 | FV54 | GD54 | GH54 | GP54 | GY54 | HF54 | AD54 | AK54 | AT54 | AY54 | BF54 | BM54 | BV54 | CD54 | CK54 | CR54 | CY54 | DF54 | DM54 | HM54 | HV54 | JB54 | JH54 | JP54 | JY54 | KF54 | KM54 | KU54 | LH54 | D54 | H54 | L54 | W54 | 235 | LR55 | LW55 | MC55 | MF55 | DJ55 | HJ55 | HR55 | HY55 | JE55 | JL55 | JU55 | KC55 | KJ55 | KW55 | LE55 | LL55 | DR55 | EA55 | EG55 | EL55 | EU55 | FC55 | FJ55 | FR55 | GA55 | GF55 | GL55 | GU55 | HC55 | KR55 | AA55 | AG55 | AN55 | AV55 | BC55 | BJ55 | BR55 | CA55 | CG55 | CN55 | CU55 | DC55 | B55 | MK55 | F55 | J55 | N55 | U55 | 236 | LB56 | LN56 | LU56 | MA56 | MD56 | MH56 | DV56 | ED56 | EJ56 | EP56 | EY56 | FF56 | FM56 | FV56 | GD56 | GH56 | GP56 | GY56 | HF56 | AD56 | AK56 | AT56 | AY56 | BF56 | BM56 | BV56 | CD56 | CK56 | CR56 | CY56 | DF56 | DM56 | HM56 | HV56 | JB56 | JH56 | JP56 | JY56 | KF56 | KM56 | KU56 | LH56 | D56 | H56 | L56 | W56 | 237 | LR57 | LW57 | MC57 | MF57 | DJ57 | HJ57 | HR57 | HY57 | JE57 | JL57 | JU57 | KC57 | KJ57 | KW57 | LE57 | LL57 | DR57 | EA57 | EG57 | EL57 | EU57 | FC57 | FJ57 | FR57 | GA57 | GF57 | GL57 | GU57 | HC57 | KR57 | AA57 | AG57 | AN57 | AV57 | BC57 | BJ57 | BR57 | CA57 | CG57 | CN57 | CU57 | DC57 | B57 | MK57 | F57 | J57 | N57 | U57 | 238 | LB58 | LN58 | LU58 | MA58 | MD58 | MH58 | DV58 | ED58 | EJ58 | EP58 | EY58 | FF58 | FM58 | FV58 | GD58 | GH58 | GP58 | GY58 | HF58 | AD58 | AK58 | AT58 | AY58 | BF58 | BM58 | BV58 | CD58 | CK58 | CR58 | CY58 | DF58 | DM58 | HM58 | HV58 | JB58 | JH58 | JP58 | JY58 | KF58 | KM58 | KU58 | LH58 | D58 | H58 | L58 | W58 | 239 | LR59 | LW59 | MC59 | MF59 | DJ59 | HJ59 | HR59 | HY59 | JE59 | JL59 | JU59 | KC59 | KJ59 | KW59 | LE59 | LL59 | DR59 | EA59 | EG59 | EL59 | EU59 | FC59 | FJ59 | FR59 | GA59 | GF59 | GL59 | GU59 | HC59 | KR59 | AA59 | AG59 | AN59 | AV59 | BC59 | BJ59 | BR59 | CA59 | CG59 | CN59 | CU59 | DC59 | B59 | MK59 | F59 | J59 | N59 | U59 | 240 | LB60 | LN60 | LU60 | MA60 | MD60 | MH60 | DV60 | ED60 | EJ60 | EP60 | EY60 | FF60 | FM60 | FV60 | GD60 | GH60 | GP60 | GY60 | HF60 | AD60 | AK60 | AT60 | AY60 | BF60 | BM60 | BV60 | CD60 | CK60 | CR60 | CY60 | DF60 | DM60 | HM60 | HV60 | JB60 | JH60 | JP60 | JY60 | KF60 | KM60 | KU60 | LH60 | D60 | H60 | L60 | W60 | 241 | LR61 | LW61 | MC61 | MF61 | DJ61 | HJ61 | HR61 | HY61 | JE61 | JL61 | JU61 | KC61 | KJ61 | KW61 | LE61 | LL61 | DR61 | EA61 | EG61 | EL61 | EU61 | FC61 | FJ61 | FR61 | GA61 | GF61 | GL61 | GU61 | HC61 | KR61 | AA61 | AG61 | AN61 | AV61 | BC61 | BJ61 | BR61 | CA61 | CG61 | CN61 | CU61 | DC61 | B61 | MK61 | F61 | J61 | N61 | U61 | LB62 | LN62 | LU62 | MA62 | MD62 | MH62 | DV62 | ED62 | EJ62 | EP62 | EY62 | FF62 | FM62 | FV62 | GD62 | GH62 | GP62 | GY62 | HF62 | AD62 | AK62 | AT62 | AY62 | BF62 | BM62 | BV62 | CD62 | CK62 | CR62 | CY62 | DF62 | DM62 | HM62 | HV62 | JB62 | JH62 | JP62 | JY62 | KF62 | KM62 | KU62 | LH62 | D62 | H62 | L62 | W62 | 242 | LR63 | LW63 | MC63 | MF63 | DJ63 | HJ63 | HR63 | HY63 | JE63 | JL63 | JU63 | KC63 | KJ63 | KW63 | LE63 | LL63 | DR63 | EA63 | EG63 | EL63 | EU63 | FC63 | FJ63 | FR63 | GA63 | GF63 | GL63 | GU63 | HC63 | KR63 | AA63 | AG63 | AN63 | AV63 | BC63 | BJ63 | BR63 | CA63 | CG63 | CN63 | CU63 | DC63 | B63 | MK63 | F63 | J63 | N63 | U63 | 243 | LB64 | LN64 | LU64 | MA64 | MD64 | MH64 | DV64 | ED64 | EJ64 | EP64 | EY64 | FF64 | FM64 | FV64 | GD64 | GH64 | GP64 | GY64 | HF64 | AD64 | AK64 | AT64 | AY64 | BF64 | BM64 | BV64 | CD64 | CK64 | CR64 | CY64 | DF64 | DM64 | HM64 | HV64 | JB64 | JH64 | JP64 | JY64 | KF64 | KM64 | KU64 | LH64 | D64 | H64 | L64 | R64 | W64 | 244 | LR65 | LW65 | MC65 | MF65 | DJ65 | HJ65 | HR65 | HY65 | JE65 | JL65 | JU65 | KC65 | KJ65 | KW65 | LE65 | LL65 | DR65 | EA65 | EG65 | EL65 | EU65 | FC65 | FJ65 | FR65 | GA65 | GF65 | GL65 | GU65 | HC65 | KR65 | AA65 | AG65 | AN65 | AV65 | BC65 | BJ65 | BR65 | CA65 | CG65 | CN65 | CU65 | DC65 | B65 | MK65 | F65 | J65 | N65 | U65 | 245 | LB66 | DV66 | ED66 | EJ66 | EP66 | EY66 | FF66 | FM66 | FV66 | GD66 | GH66 | GP66 | GY66 | HF66 | AK66 | AT66 | AY66 | BF66 | BM66 | BV66 | CD66 | CK66 | CR66 | CY66 | DF66 | DM66 | HM66 | HV66 | JB66 | JH66 | JP66 | JY66 | KF66 | KM66 | KU66 | LH66 | G67 | M67 | Y67 | LP67 | LV67 | MG67 | ML67 | T67 | MB67 | 246 | DJ68 | HJ68 | HR68 | HY68 | JE68 | JL68 | JU68 | KC68 | DR68 | EA68 | EG68 | EL68 | EU68 | FC68 | FJ68 | FR68 | GA68 | GF68 | GL68 | GU68 | HC68 | KJ68 | KR68 | KW68 | LE68 | AG68 | AN68 | AV68 | BC68 | BJ68 | BR68 | CA68 | CG68 | CN68 | CU68 | DC68 | A69 | E69 | K69 | P69 | V69 | LM69 | LT69 | LY69 | ME69 | MJ69 | 247 | JY70 | KF70 | KM70 | KU70 | LB70 | DV70 | ED70 | EJ70 | EP70 | EY70 | FF70 | FM70 | FV70 | GD70 | GH70 | GP70 | GY70 | HF70 | AK70 | AT70 | AY70 | BF70 | BM70 | BV70 | CD70 | CK70 | CR70 | CY70 | DF70 | DM70 | HM70 | HV70 | JB70 | JH70 | JP70 | G71 | M71 | Y71 | LK71 | LP71 | LV71 | MG71 | ML71 | T71 | MB71 | 248 | A72 | E72 | K72 | P72 | V72 | AC72 | AJ72 | AR72 | BB72 | BH72 | BP72 | BY72 | CF72 | CM72 | CW72 | DE72 | DL72 | DU72 | EC72 | EK72 | ET72 | FB72 | FH72 | FP72 | FY72 | GG72 | GN72 | GW72 | HE72 | HL72 | HU72 | JD72 | JK72 | JT72 | KB72 | KH72 | KP72 | LA72 | LG72 | LM72 | LT72 | LY72 | ME72 | MJ72 | 249 | 105 | G73 | M73 | Y73 | AF73 | AM73 | AW73 | BE73 | BL73 | BU73 | CC73 | CJ73 | CT73 | DB73 | DH73 | DP73 | DY73 | EF73 | EN73 | EW73 | FE73 | FL73 | FU73 | GC73 | GK73 | GT73 | HB73 | HH73 | HP73 | JA73 | JG73 | JN73 | JW73 | KE73 | KL73 | KV73 | LD73 | LK73 | LP73 | LV73 | MG73 | ML73 | T73 | MB73 | 250 | 106 | A74 | E74 | K74 | P74 | V74 | AC74 | AJ74 | AR74 | BB74 | BH74 | BP74 | BY74 | CF74 | CM74 | CW74 | DE74 | DL74 | DU74 | EC74 | EK74 | ET74 | FB74 | FH74 | FP74 | FY74 | GG74 | GN74 | GW74 | HE74 | HL74 | HU74 | JD74 | JK74 | JT74 | KB74 | KH74 | KP74 | LA74 | LG74 | LM74 | LT74 | LY74 | ME74 | MJ74 | 251 | 107 | 252 | 108 | G75 | M75 | Y75 | AF75 | AM75 | AW75 | BE75 | BL75 | BU75 | CC75 | CJ75 | CT75 | DB75 | KL75 | KV75 | LD75 | LK75 | LP75 | LV75 | MG75 | ML75 | T75 | DH75 | DP75 | DY75 | EF75 | EN75 | EW75 | FE75 | FL75 | FU75 | GC75 | GK75 | GT75 | HB75 | HH75 | HP75 | JA75 | JG75 | JN75 | JW75 | KE75 | MB75 | 253 | 109 | A76 | E76 | K76 | P76 | V76 | AC76 | AJ76 | AR76 | BB76 | BH76 | BP76 | BY76 | CF76 | CM76 | CW76 | DE76 | DL76 | DU76 | EC76 | EK76 | ET76 | FB76 | FH76 | FP76 | FY76 | GG76 | GN76 | GW76 | HE76 | HL76 | HU76 | JD76 | JK76 | JT76 | KB76 | KH76 | KP76 | LA76 | LG76 | LM76 | LT76 | LY76 | ME76 | MJ76 | 254 | 110 | G77 | M77 | Y77 | AF77 | AM77 | AW77 | BE77 | BL77 | BU77 | CC77 | CJ77 | CT77 | DB77 | KL77 | KV77 | LD77 | LK77 | LP77 | LV77 | MG77 | ML77 | T77 | MB77 | DH77 | DP77 | DY77 | EF77 | EN77 | EW77 | FE77 | FL77 | FU77 | GC77 | GK77 | GT77 | HB77 | HH77 | HP77 | JA77 | JG77 | JN77 | JW77 | KE77 | 255 | 111 | A78 | E78 | K78 | P78 | V78 | AC78 | AJ78 | AR78 | BB78 | BH78 | BP78 | BY78 | CF78 | CM78 | CW78 | DE78 | DL78 | DU78 | EC78 | EK78 | ET78 | FB78 | FH78 | FP78 | FY78 | GG78 | GN78 | GW78 | HE78 | HL78 | HU78 | JD78 | JK78 | JT78 | KB78 | KH78 | KP78 | LA78 | LG78 | LM78 | LT78 | LY78 | ME78 | MJ78 | 256 | 112 | G79 | M79 | Y79 | AF79 | AM79 | AW79 | BE79 | BL79 | BU79 | CC79 | CJ79 | CT79 | DB79 | KL79 | KV79 | LD79 | LK79 | LP79 | LV79 | MG79 | ML79 | T79 | MB79 | DH79 | DP79 | DY79 | EF79 | EN79 | EW79 | FE79 | FL79 | FU79 | GC79 | GK79 | GT79 | HB79 | HH79 | HP79 | JA79 | JG79 | JN79 | JW79 | KE79 | 257 | 113 | A80 | E80 | K80 | P80 | V80 | AC80 | AJ80 | AR80 | BB80 | BH80 | BP80 | BY80 | CF80 | CM80 | CW80 | DE80 | DL80 | DU80 | EC80 | EK80 | ET80 | FB80 | FH80 | FP80 | FY80 | GG80 | GN80 | GW80 | HE80 | HL80 | HU80 | JD80 | JK80 | JT80 | KB80 | KH80 | KP80 | LA80 | LG80 | LM80 | LT80 | LY80 | ME80 | MJ80 | 258 | 114 | G81 | M81 | Y81 | AF81 | AM81 | AW81 | BE81 | BL81 | BU81 | CC81 | CJ81 | CT81 | DB81 | KL81 | KV81 | LD81 | LK81 | LP81 | LV81 | MG81 | ML81 | T81 | MB81 | DH81 | DP81 | DY81 | EF81 | EN81 | EW81 | FE81 | FL81 | FU81 | GC81 | GK81 | GT81 | HB81 | HH81 | HP81 | JA81 | JG81 | JN81 | JW81 | KE81 | 259 | 115 | A82 | E82 | K82 | P82 | V82 | AC82 | AJ82 | AR82 | BB82 | BH82 | BP82 | BY82 | CF82 | CM82 | CW82 | DE82 | DL82 | DU82 | EC82 | EK82 | ET82 | FB82 | FH82 | FP82 | FY82 | GG82 | GN82 | GW82 | HE82 | HL82 | HU82 | JD82 | JK82 | JT82 | KB82 | KH82 | KP82 | LA82 | LG82 | LM82 | LT82 | LY82 | ME82 | MJ82 | 260 | 116 | G83 | M83 | Y83 | AF83 | AM83 | AW83 | BE83 | BL83 | BU83 | CC83 | CJ83 | CT83 | DB83 | KL83 | KV83 | LD83 | LK83 | LP83 | LV83 | MG83 | T83 | MB83 | DH83 | DP83 | DY83 | EF83 | EN83 | EW83 | FE83 | FL83 | FU83 | GC83 | GK83 | GT83 | HB83 | HH83 | HP83 | JA83 | JG83 | JN83 | JW83 | KE83 | 261 | 117 | 262 | 118 | 263 | 119 | 264 | 120 | 265 | 121 | 266 | 122 | 267 | 123 | 268 | 124 | 269 | 125 | 270 | 126 | 271 | 127 | 272 | 128 | 273 | 129 | 274 | 130 | 275 | 131 | 276 | 132 | 277 | 133 | 278 | 134 | 279 | 135 | 280 | 136 | 281 | 137 | 282 | 138 | 283 | 139 | 284 | 140 | 285 | 141 | 286 | 142 | 287 | 143 | 288 | 144 | PAD-070RD047 | 053SQ031 | 053RD031 | PAD-HOLE118NPT | 090SQ071 | 090RD071 | ADC_VREF | PWM | HSSI_PWM | PCIE_PERSTn | FX2_RESETn | CPU_RESETn | GXF_PERSTn | CXL_PERSTn | C1361 | C1376 | C770 | C693 | L18 | C1375 | CN4 | C859 | X1 | X4 | X8 | X16 | C636 | C634 | C635 | U19 | A48 | OPEN = ENABLE | CLOSED = DISABLE | D5 | E5 | E4 | C1381 | C1354 | C1355 | C1005 | D10 | D6 | ON | OFF | C584 | C574 | C580 | C585 | C590 | Q13 | C623 | U50 | C583 | C592 | U69 | C588 | L21 | U89 | C622 | C625 | C621 | C624 | U60 | C640 | C659 | C678 | C704 | B82 | B48 | U75 | Y1 | U71 | U23 | U28 | U32 | Q10 | Q8 | Q7 | C594 | C742 | C741 | C1002 | U52 | Q14 | C591 | C1003 | C831 | C596 | D13 | C844 | R77 | R78 | R95 | R96 | C595 | CLOSE --> SELECT | E | F | T | OPEN --> DESELECT | C843 | CN6 | CN5 | PCIE_EP_PRSNT | C586 | C637 | EU2 | CN2 | CN3 | C97 | C878 | CN1 | U81 | C814 | U84 | L5 | L6 | U87 | U88 | Q6 | Config Mode | Q4 | AVST x8 | JTAG | Q5 | U38 | Q3 | MSEL2 | U62 | Q2 | MSEL1 | MSEL0 | Q1 | JTAG MASTER | MSEL | C593 | H | K | M | P | J | L | N | R | MK | A81 | B81 | B80 | A79 | B79 | B78 | A77 | B77 | B76 | A75 | B75 | B74 | A73 | B73 | B72 | A71 | B71 | A70 | B70 | B69 | A68 | B68 | A67 | B67 | A66 | B66 | A65 | A64 | B64 | A63 | A62 | B62 | A61 | A60 | B60 | A59 | A58 | B58 | A57 | A56 | B56 | A55 | A54 | B54 | A53 | A52 | B52 | A51 | A50 | B50 | A49 | A47 | A46 | B46 | A45 | A44 | B44 | A43 | A42 | B42 | A41 | A40 | B40 | A39 | A38 | B38 | T16 | P16 | N16 | M16 | L16 | K16 | J16 | H16 | G16 | F16 | E16 | D16 | T15 | P15 | N15 | M15 | K15 | J15 | G15 | F15 | E15 | T14 | P14 | N14 | M14 | K14 | J14 | H14 | G14 | F14 | E14 | D14 | T13 | P13 | M13 | K13 | H13 | G13 | E13 | T12 | R12 | P12 | N12 | M12 | K12 | J12 | H12 | G12 | F12 | E12 | D12 | T11 | P11 | N11 | M11 | K11 | J11 | G11 | F11 | E11 | T10 | P10 | N10 | M10 | L10 | K10 | J10 | H10 | G10 | F10 | E10 | T6 | R6 | P6 | N6 | M6 | K6 | J6 | H6 | G6 | F6 | E6 | T5 | R5 | P5 | M5 | K5 | H5 | G5 | T4 | P4 | N4 | M4 | K4 | J4 | G4 | F4 | MF | MTH1 | U66 | U68 | L20 | U24 | L22 | U22 | PCB EDGE | SPECIALPADSTACKS | smd022x010/smd280sq | PADSTACK-SMT020SQ | SMT050X070 | 060SQ016 | SMT050X110 | SMT033X037 | SW5 | SW4 | SW3 | SW2 | SW1 | DDR4 DUAL DIMM A | DDR4 DUAL DIMM B | SMT040X056 | POWER_INPUT | GND | 12.5A | 12V_AUX | POWER_ON | FAN_CTRL | SW6 | MTH4 | U64 | U83 | U67 | U82 | U54 | U70 | U11 | U10 | U58 | U56 | L17 | U8 | U7 | U1 | U6 | U3 | U4 | U72 | U73 | U30 | U34 | U36 | U42 | U18 | 100-0330672-A1 RevA1 | U12 | U15 | U16 | U40 | U14 | MTH5 | MTH2 | U20 | U86 | 2LI | Agilex  I-Series FPGA
User.19: POWER | 1 | 3 | 2 | 0 | FPGA_3V3 | 4 | ON | OFF | 8 | 5 | TDI | D9:OVERTEMPn | D11:FPGA_CONF_DONE | ENPIRION DONGLE | TMS | CLK_IN | CLK_OUT | TDO | EXTERNAL JTAG | A37 | TCK | B1 | B37 | A | 6 | B | 11 | 21 | 31 | TM | B82 | B48 | B31 | 7 | 12 | 19 | 26 | B17 | C | 17 | D | 25 | 32 | Y | D4 | G | QSFPDD1 | D3 | D2 | D1 | QSFPDD0 | 15 | 14 | 29 | 42 | 43 | 56 | 50 | 51 | E | 10 | 9 | 81 | 82 | 100 | 22 | F | 40 | 145 | H | K | M | P | T | J | L | N | R | 39 | 30 | 20 | MK | 221 | 77 | 222 | 78 | 83 | 23 | 288 | 144 | 38 | 58 | 76 | 57 | 28 | 16 | 13 | CXL_PERSTn | GXF_PERSTn | CPU_RESETn | FX2_RESETn | PCIE_PERSTn | HSSI_PWM | PWM | 33 | ADC_VREF | PCB EDGE | DDR4 DUAL DIMM B | DDR4 DUAL DIMM A | FAN_CTRL | POWER_ON | 12V_AUX | 12.5A | GND | POWER_INPUT | 2LI | Agilex  I-Series FPGA | PRIMARY SIDE SILKSCREEN
User.21: INTERNAL SIGNAL LAYER 3
User.22: INTERNAL GND PLANE LAYER 2
User.24: PRIMARY SIDE PASTE MASK
User.25: SECONDARY SIDE PASTE MASK
User.26: PRIMARY SIDE SILKSCREEN
User.27: SECONDARY SIDE SILKSCREEN
User.28: PRIMARY SIDE SOLDERMASK
User.29: SECONDARY SIDE SOLDERMASK
User.30: INTERNAL PWR PLANE LAYER 10
User.31: INTERNAL GND PLANE LAYER 11
User.32: INTERNAL SIGNAL LAYER 12
User.33: INTERNAL GND PLANE LAYER 13
User.34: INTERNAL SIGNAL LAYER 14
User.35: INTERNAL GND PLANE LAYER 15
User.36: INTERNAL SIGNAL LAYER 16
User.37: INTERNAL GND PLANE LAYER 17
User.38: INTERNAL XXX LAYER 18
User.39: INTERNAL XXX LAYER 19
User.40: INTERNAL XXX LAYER 20
User.41: INTERNAL XXX LAYER 21
User.42: INTERNAL XXX LAYER 22
User.43: INTERNAL XXX LAYER 23
User.44: INTERNAL XXX LAYER 24
